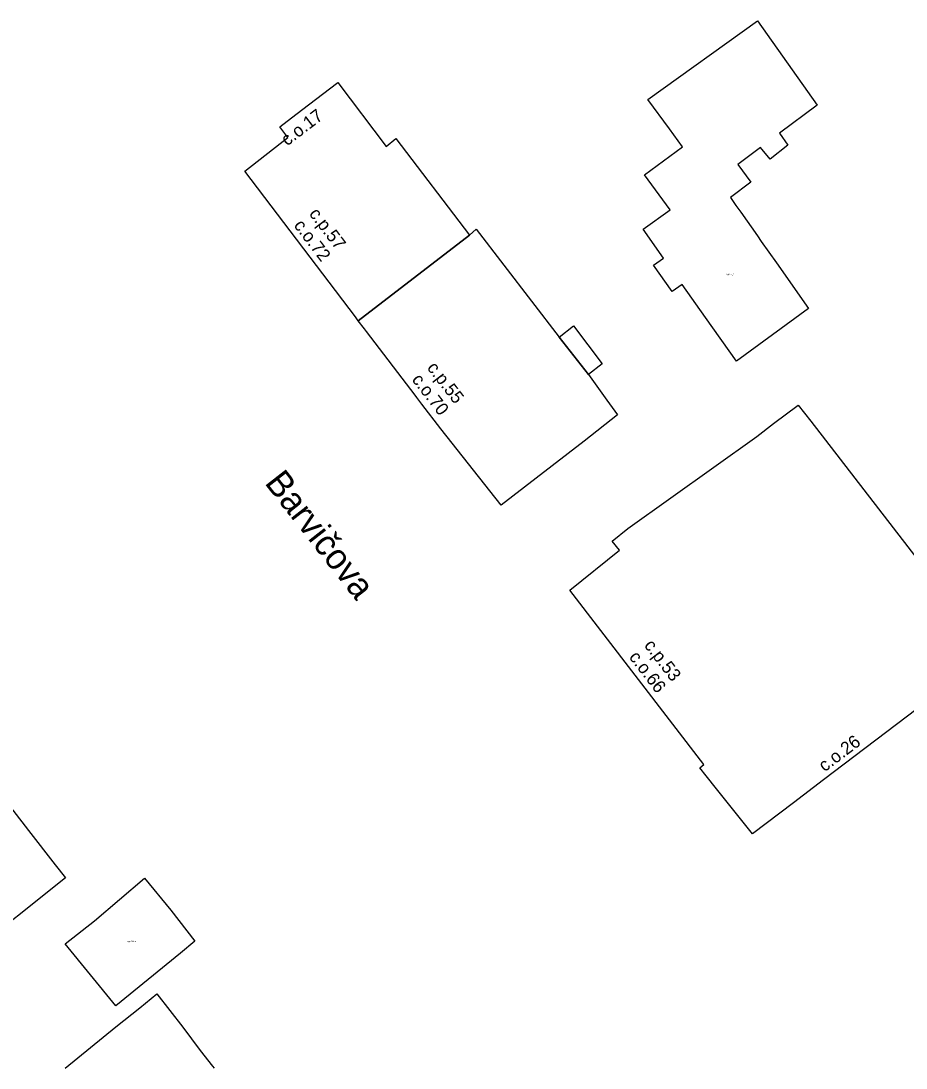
# Model space of a CAD drawing. Extents: x -600391 to -599491, y -1160176 to -1159402.
# Drawn here: x -600213.3 to -600144.1, y -1160176.1 to -1160094.3 of the extents above; entities that cross this region are included whole.
import ezdxf

# ---------------------------------------------------------------- set-up
doc = ezdxf.new("R2010")
doc.units = 0
for name, color, linetype in [('Level 10', 7, 'Continuous'), ('Level 11', 7, 'Continuous'), ('Level 12', 7, 'Continuous'), ('Level 25', 7, 'Continuous'), ('Level 61', 7, 'Continuous'), ('Level 62', 7, 'Continuous')]:
    doc.layers.add(name, color=color, linetype=linetype)

msp = doc.modelspace()

# ---------------------------------------------------------------- linework, layer by layer
at = {"layer": 'Level 61'}
for p, q in [((-600209.838, -1160176.079), (-600205.87, -1160172.87)), ((-600198.32, -1160175.92), (-600198.197, -1160176.079))]:
    msp.add_line(p, q, dxfattribs=at)
for points in [[(-600164.32, -1160100.41), (-600155.74, -1160094.26)], [(-600155.74, -1160094.26), (-600151.09, -1160100.85)], [(-600190.81, -1160100.81), (-600188.52, -1160099.08)], [(-600188.52, -1160099.08), (-600184.76, -1160104.07)], [(-600192.15, -1160101.83), (-600190.81, -1160100.81)], [(-600162.63, -1160102.7), (-600164.32, -1160100.41)], [(-600151.09, -1160100.85), (-600154.02, -1160103.04)], [(-600193.07, -1160102.53), (-600192.15, -1160101.83)], [(-600192.43, -1160103.36), (-600193.07, -1160102.53)], [(-600161.6, -1160104.09), (-600162.63, -1160102.7)], [(-600195.79, -1160105.99), (-600192.43, -1160103.36)], [(-600184.76, -1160104.07), (-600183.99, -1160103.45)], [(-600183.99, -1160103.45), (-600178.25, -1160111)], [(-600154.02, -1160103.04), (-600153.38, -1160103.96)], [(-600164.57, -1160106.29), (-600161.6, -1160104.09)], [(-600155.51, -1160104.16), (-600157.29, -1160105.49)], [(-600154.76, -1160105.05), (-600155.51, -1160104.16)], [(-600153.38, -1160103.96), (-600154.76, -1160105.05)], [(-600187.14, -1160117.38), (-600195.79, -1160105.99)], [(-600157.29, -1160105.49), (-600156.27, -1160106.85)], [(-600162.57, -1160109.02), (-600164.57, -1160106.29)], [(-600156.27, -1160106.85), (-600157.87, -1160108.05)], [(-600157.87, -1160108.05), (-600157.43, -1160108.68)], [(-600164.69, -1160110.52), (-600162.57, -1160109.02)], [(-600157.43, -1160108.68), (-600157.06, -1160109.21)], [(-600157.06, -1160109.21), (-600155.76, -1160111.05)], [(-600178.25, -1160111), (-600177.73, -1160110.53)], [(-600177.73, -1160110.53), (-600171.25, -1160118.98)], [(-600163.08, -1160112.8), (-600164.69, -1160110.52)], [(-600186.94, -1160117.69), (-600178.25, -1160111)], [(-600178.25, -1160111), (-600186.94, -1160117.69)], [(-600155.76, -1160111.05), (-600155.45, -1160111.5)], [(-600155.45, -1160111.5), (-600154.26, -1160113.17)], [(-600163.86, -1160113.35), (-600163.08, -1160112.8)], [(-600162.41, -1160115.39), (-600163.86, -1160113.35)], [(-600154.26, -1160113.17), (-600151.76, -1160116.73)], [(-600161.64, -1160114.85), (-600162.41, -1160115.39)], [(-600159.81, -1160117.43), (-600161.64, -1160114.85)], [(-600186.94, -1160117.69), (-600187.14, -1160117.38)], [(-600157.4, -1160120.85), (-600159.81, -1160117.43)], [(-600151.76, -1160116.73), (-600157.4, -1160120.85)], [(-600186.45, -1160118.32), (-600186.94, -1160117.69)], [(-600171.25, -1160118.98), (-600170.12, -1160118.08)], [(-600170.12, -1160118.08), (-600167.89, -1160121.04)], [(-600186.3, -1160118.52), (-600186.45, -1160118.32)], [(-600182.5, -1160123.49), (-600186.3, -1160118.52)], [(-600168.96, -1160121.89), (-600171.25, -1160118.98)], [(-600171.25, -1160118.98), (-600168.96, -1160121.89)], [(-600167.89, -1160121.04), (-600168.96, -1160121.89)], [(-600168.96, -1160121.89), (-600167.52, -1160123.89)], [(-600182.35, -1160123.69), (-600182.5, -1160123.49)], [(-600181.96, -1160124.2), (-600182.35, -1160123.69)], [(-600167.52, -1160123.89), (-600166.68, -1160125.04)], [(-600180.49, -1160126.12), (-600181.96, -1160124.2)], [(-600154.49, -1160125.71), (-600152.56, -1160124.27)], [(-600152.56, -1160124.27), (-600151.58, -1160125.54)], [(-600166.68, -1160125.04), (-600169.29, -1160127.09)], [(-600151.58, -1160125.54), (-600137.57, -1160143.69)], [(-600175.78, -1160132.1), (-600180.49, -1160126.12)], [(-600155.79, -1160126.72), (-600154.49, -1160125.71)], [(-600169.29, -1160127.09), (-600170.55, -1160128.06)], [(-600165.88, -1160133.93), (-600155.79, -1160126.72)], [(-600170.55, -1160128.06), (-600173.04, -1160129.98)], [(-600173.04, -1160129.98), (-600175.78, -1160132.1)], [(-600167.09, -1160134.9), (-600165.88, -1160133.93)], [(-600166.52, -1160135.6), (-600167.09, -1160134.9)], [(-600170.41, -1160138.74), (-600166.52, -1160135.6)], [(-600159.94, -1160152.37), (-600170.41, -1160138.74)], [(-600137.57, -1160143.69), (-600150.59, -1160153.57)], [(-600160.25, -1160152.62), (-600159.94, -1160152.37)], [(-600159.75, -1160153.24), (-600160.25, -1160152.62)], [(-600158.95, -1160154.26), (-600159.75, -1160153.24)], [(-600156.14, -1160157.79), (-600158.95, -1160154.26)], [(-600150.59, -1160153.57), (-600152.93, -1160155.35)], [(-600213.93, -1160155.94), (-600212.69, -1160157.52)], [(-600152.93, -1160155.35), (-600156.14, -1160157.79)], [(-600212.69, -1160157.52), (-600210.6, -1160160.2)], [(-600210.6, -1160160.2), (-600209.81, -1160161.21)], [(-600209.81, -1160161.21), (-600217.46, -1160167.3)], [(-600207.53, -1160164.58), (-600203.62, -1160161.24)], [(-600203.62, -1160161.24), (-600201.57, -1160163.74)], [(-600201.57, -1160163.74), (-600199.69, -1160166.16)], [(-600209.82, -1160166.38), (-600207.53, -1160164.58)], [(-600207.84, -1160168.79), (-600209.82, -1160166.38)], [(-600199.69, -1160166.16), (-600200.83, -1160167.09)], [(-600200.83, -1160167.09), (-600205.86, -1160171.22)], [(-600205.86, -1160171.22), (-600207.84, -1160168.79)], [(-600204.01, -1160171.37), (-600202.68, -1160170.29)], [(-600202.68, -1160170.29), (-600200.65, -1160172.89)], [(-600205.87, -1160172.87), (-600204.01, -1160171.37)], [(-600200.65, -1160172.89), (-600199.28, -1160174.7)], [(-600199.28, -1160174.7), (-600198.32, -1160175.92)]]:
    msp.add_lwpolyline(points, dxfattribs=at)
at = {"layer": 'Level 62'}
for points in [[(-600155.74, -1160094.26), (-600151.09, -1160100.85), (-600154.02, -1160103.04), (-600153.38, -1160103.96), (-600154.76, -1160105.05), (-600155.51, -1160104.16), (-600157.29, -1160105.49), (-600156.27, -1160106.85), (-600157.87, -1160108.05), (-600157.43, -1160108.68), (-600157.06, -1160109.21), (-600155.76, -1160111.05), (-600155.45, -1160111.5), (-600154.26, -1160113.17), (-600151.76, -1160116.73), (-600157.4, -1160120.85), (-600159.81, -1160117.43), (-600161.64, -1160114.85), (-600162.41, -1160115.39), (-600163.86, -1160113.35), (-600163.08, -1160112.8), (-600164.69, -1160110.52), (-600162.57, -1160109.02), (-600164.57, -1160106.29), (-600161.6, -1160104.09), (-600162.63, -1160102.7), (-600164.32, -1160100.41), (-600155.74, -1160094.26)], [(-600190.81, -1160100.81), (-600188.52, -1160099.08), (-600184.76, -1160104.07), (-600183.99, -1160103.45), (-600178.25, -1160111), (-600186.94, -1160117.69), (-600187.14, -1160117.38), (-600195.79, -1160105.99), (-600192.43, -1160103.36), (-600193.07, -1160102.53), (-600192.15, -1160101.83), (-600190.81, -1160100.81)], [(-600169.29, -1160127.09), (-600170.55, -1160128.06), (-600173.04, -1160129.98), (-600175.78, -1160132.1), (-600180.49, -1160126.12), (-600181.96, -1160124.2), (-600182.35, -1160123.69), (-600182.5, -1160123.49), (-600186.3, -1160118.52), (-600186.45, -1160118.32), (-600186.94, -1160117.69), (-600178.25, -1160111), (-600177.73, -1160110.53), (-600171.25, -1160118.98), (-600168.96, -1160121.89), (-600167.52, -1160123.89), (-600166.68, -1160125.04), (-600169.29, -1160127.09)], [(-600168.96, -1160121.89), (-600171.25, -1160118.98), (-600170.12, -1160118.08), (-600167.89, -1160121.04), (-600168.96, -1160121.89)], [(-600155.79, -1160126.72), (-600154.49, -1160125.71), (-600152.56, -1160124.27), (-600151.58, -1160125.54), (-600137.57, -1160143.69), (-600150.59, -1160153.57), (-600152.93, -1160155.35), (-600156.14, -1160157.79), (-600158.95, -1160154.26), (-600159.75, -1160153.24), (-600160.25, -1160152.62), (-600159.94, -1160152.37), (-600170.41, -1160138.74), (-600166.52, -1160135.6), (-600167.09, -1160134.9), (-600165.88, -1160133.93), (-600155.79, -1160126.72)], [(-600214.49, -1160155.22), (-600213.93, -1160155.94), (-600212.69, -1160157.52), (-600210.6, -1160160.2), (-600209.81, -1160161.21), (-600217.46, -1160167.3), (-600223.73, -1160159.37), (-600222.61, -1160158.36), (-600216.09, -1160153.17), (-600214.49, -1160155.22)], [(-600203.62, -1160161.24), (-600201.57, -1160163.74), (-600199.69, -1160166.16), (-600200.83, -1160167.09), (-600205.86, -1160171.22), (-600207.84, -1160168.79), (-600209.82, -1160166.38), (-600207.53, -1160164.58), (-600203.62, -1160161.24)], [(-600209.838, -1160176.079), (-600205.87, -1160172.87), (-600204.01, -1160171.37), (-600202.68, -1160170.29), (-600200.65, -1160172.89), (-600199.28, -1160174.7), (-600198.32, -1160175.92), (-600198.197, -1160176.079)]]:
    msp.add_lwpolyline(points, dxfattribs=at)

# ---------------------------------------------------------------- texts
at = {"layer": 'Level 10'}
for s, rotation, p in [('c.o.17', 37.20108, (-600192.489, -1160104.067)), ('c.o.72', 307.21367, (-600192.015, -1160110.247)), ('c.o.70', 307.65942, (-600182.797, -1160122.298)), ('c.o.66', 307.53226, (-600165.829, -1160143.976)), ('c.o.26', 37.19305, (-600150.507, -1160152.973))]:
    msp.add_text(s, height=1, rotation=rotation, dxfattribs=at).set_placement(p)
at = {"layer": 'Level 11'}
msp.add_text('Barvičova', height=2, rotation=308.00531, dxfattribs=at).set_placement((-600194.305, -1160130.366))
at = {"layer": 'Level 12'}
for s, rotation, p in [('c.p.57', 307.21367, (-600190.822, -1160109.338)), ('c.p.55', 307.65941, (-600181.611, -1160121.375)), ('c.p.53', 307.53226, (-600164.649, -1160143.063))]:
    msp.add_text(s, height=1, rotation=rotation, dxfattribs=at).set_placement(p)
at = {"layer": 'Level 25'}
for s, p in [('c.pp.55_A', (-600158.187, -1160114.097)), ('c.pp.639_A', (-600205.003, -1160166.227))]:
    msp.add_text(s, height=0.1, dxfattribs=at).set_placement(p)

doc.saveas('drawing.dxf')
